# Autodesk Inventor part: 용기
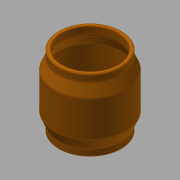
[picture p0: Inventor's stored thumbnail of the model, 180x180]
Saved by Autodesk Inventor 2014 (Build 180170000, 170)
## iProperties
Created: 2018-01
Part Number: 용기
Material: ABS 플라스틱
Document SubType Name: Modeling
Designer: mduedu
Density: 1 g/cm^3
Appearance: 주황색
Author: mduedu
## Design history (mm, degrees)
sketch "스케치1"
  geometry: L1 (0, 0)-(-35, 0); L2 (-35, 0)-(-35, 8); L3 (-35, 8)-(-40, 20); L4 (-40, 20)-(-40, 60); L5 (-40, 60)-(-35, 72); L6 (-35, 72)-(-35, 80); L7 (-35, 80)-(0, 80); L8 (0, 80)-(0, 0)
  constraints: 16 end point, 3 collinear, 3 parallel, 1 horizontal, 1 perpendicular
  dimensions: "d0" = 8 distance of L1.end L2.end; "d2" = 70 diameter of L2 L8; "d3" = 20 distance from line of L3.end L1; "d4" = 60 distance from line of L4.end L1; "d5" = 20 distance from line of L4.end L7; "d6" = 80 diameter of L4 L8
revolve "회전1" sketch "스케치1" stored, may be unused: angle "d7" = 90 deg
fillet "모깎기1" dims "d8" = 3
feature "쉘1" dims "d9" = 4
fillet "모깎기2" dims "d10" = 1
chamfer "모따기1" distance "d11" = 0.5; stored, may be unused: second distance "d12" = 2, angle "d13" = 45 deg
node "솔리드1"
